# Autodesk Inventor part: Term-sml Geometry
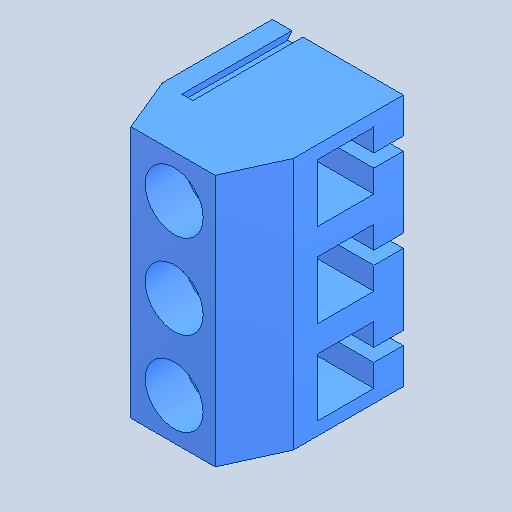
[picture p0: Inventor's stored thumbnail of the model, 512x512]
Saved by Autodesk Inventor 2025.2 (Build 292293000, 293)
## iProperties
Created: 2025-04
Part Number: Term-sml Geometry
Material: Generic
Description: PART-Term-sml Geometry-DESC
Document SubType Name: Modeling
Designer: BennF
Density: 1 g/cm^3
Appearance: Default
Author: BennF
Revision Number: NONE
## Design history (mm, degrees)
feature "Solid1"
body "Solid2"
